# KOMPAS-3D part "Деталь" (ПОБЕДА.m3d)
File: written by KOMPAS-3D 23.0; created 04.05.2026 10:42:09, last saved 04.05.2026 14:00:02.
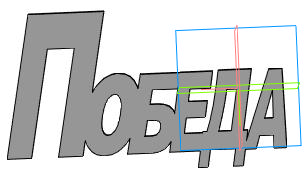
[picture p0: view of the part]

Document properties: Автор: Учитель; Полное имя файла: C:\Users\Учитель\Desktop\ПОБЕДА.m3d

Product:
- Part/product: Деталь
    Масса: 0.134991

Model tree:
1. Эскиз:1
2. Элемент выдавливания:1
     Расстояние 1 = 5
